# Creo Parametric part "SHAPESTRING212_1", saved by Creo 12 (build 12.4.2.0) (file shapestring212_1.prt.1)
Units: Custom; MM, KILOGRAM, SECS

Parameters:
  PTC_WM_ITERATION = "0"
  PTC_WM_VERSION = "-.0"
  PTC_WM_LIFECYCLE_STATE = "In Work"
  PTC_WM_LIFECYCLE = "MO_CADDocument"
  PTC_WM_CREATED_BY = "Maximilian Roepper (Z0017RMS: MO)"
  PTC_WM_CREATED_ON = "18-Sep-26 11:36:42 AM"
  PTC_WM_MODIFIED_BY = "Maximilian Roepper (Z0017RMS: MO)"
  PTC_WM_MODIFIED_ON = "18-Sep-26 11:36:46 AM"
  PDMLINKNUMBER = "PDM000071454814"
  PTC_WM_NAME = "shapestring212_1.prt"
  PTC_WM_NUMBER = "PDM000071454814"

Other parameters: WEIGHT, WEIGHT_FACTOR, WEIGHT_ADD, _MASS_TEMP, _DIFF_TEMP, MC_ERRORS, SUPPLIER

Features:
  1. coordinate system
  2. datum plane "PRT_YZ"
  3. datum plane "PRT_XY"
  4. datum plane "PRT_XZ"
  5. coordinate system
  6. datum axis
  7. datum axis
  8. datum axis
  9. coordinate system
  10. imported feature

Other named items: PRT, SIEMENS_MO, DRW_VIEW_ORG, PRT_X, PRT_Y, PRT_Z, CS0, ROUGH_GROB

Layers: 00_STD_CSYS-KSYS, 01_STD_PLANES-EBENEN, 02_STD_AXES-ACHSEN, 03_STD_CSYS-KSYS, 24_IMPORT_FEAT-IMPORT_KE, INTFCLR

Surfaces: 1 plane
